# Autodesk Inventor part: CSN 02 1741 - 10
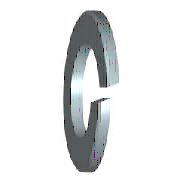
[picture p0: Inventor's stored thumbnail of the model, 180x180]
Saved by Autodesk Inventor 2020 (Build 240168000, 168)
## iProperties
Created: 2019-01
Part Number: CSN 02 1741 - 10
Material: Ocel, měkká
Description: Pružné podložky obdélníkového průřezu
Document SubType Name: Modeling
Standard: CSN 02 1741
Designer: doma
Standards Organization: CSN
Language: cs-CZ
Size Designation: 10
Categories: <MemberInstance><Categories><Category DisplayName="Spojovací materiál" InternalName="e4da775c-781d-43d5-af7c-5136215cf5a6" Mnemonic="FSTN"><Category DisplayName
Density: 7.85 g/cm^3
Appearance: Pololeštěná
Mass: 2.54828 g
Surface Area: 4.96288 cm^2
Volume: 0.324622 cm^3
IsCustomPart: 0
Author: doma
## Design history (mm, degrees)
sketch "Náčrt1"
  geometry: C1 r 8.6 at (0, 0); C2 r 5.1 at (0, 0); 1 further point
  constraints: 2 centre point, 2 coincident
  dimensions: "d0" = 10.2 diameter of C2 (= SD1); "d1" = 17.2 diameter of C1 (= SD2)
extrude "Těleso" new body sketch "Náčrt1" distance "d2" = 2.2 (= SD); taper "d3" = 0 deg
sketch "Náčrt2"
  geometry: L1 (0, -5.1)-(0, 5.1) reference; L2 (2.2, 8.6)-(2.2, -8.6) reference; L3 (-1.2, 0)-(7.2, 0) reference; L4 (0, -0.44)-(2.2, -0.052); L5 (0, 0.44)-(2.2, 0.828)
  constraints: 4 end point, 4 point on line, 1 parallel
  dimensions: "d4" = 0.44 distance from line of L3 L4.start (= 0.2 x SD); "d5" = 0.44 distance from line of L3 L5.start (= 0.2 x SD); "d6" = 80 deg angle of L2 L4 (= FAWI)
extrude "Výřez" cut sketch "Náčrt2" stored distance "d7" = 2.2 (= SD); taper "d8" = 0 deg
workaxis "Work Axis1"
workplane "Work Plane1"
body "Solid1"
other parameters: "SD1" = 10.2 [user parameter; used in 1 equation term], "SD2" = 17.2 [user parameter; used in 1 equation term], "SD" = 2.2 [user parameter; used in 4 equation terms], "FAWI" = 80 deg [user parameter; used in 1 equation term], "d9" = 0, "d10" = 0, "d11" = 0, "d12" = 0
